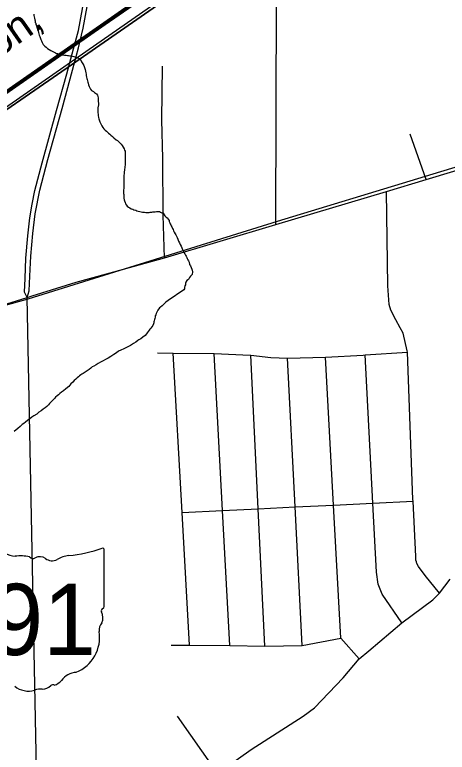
# Model space of a CAD drawing. Extents: x 0 to 44.3, y 0 to 22.
# Drawn here: x 3.367 to 4.168, y 16.349 to 17.715 of the extents above; entities that cross this region are included whole.
import ezdxf

# ---------------------------------------------------------------- set-up
doc = ezdxf.new("R2010")
doc.units = 0
for name, color, linetype in [('GM_X_City_Street', 7, 'Continuous'), ('GM_X_Corporation', 7, 'Continuous'), ('GM_X_County_Road', 7, 'Continuous'), ('GM_X_Minor_River', 7, 'Continuous'), ('GM_X_Rail_Line', 7, 'Continuous'), ('GM_X_Rail_Line_Text', 7, 'Continuous'), ('GM_X_State_Location', 7, 'Continuous'), ('GM_X_State_Route', 7, 'Continuous'), ('GM_X_State_Shield', 7, 'Continuous'), ('GM_X_US_Route', 7, 'Continuous')]:
    doc.layers.add(name, color=color, linetype=linetype)

msp = doc.modelspace()

# ---------------------------------------------------------------- linework, layer by layer
at = {"layer": 'GM_X_City_Street'}
for p, q in [((4.1283, 17.4097), (4.099, 17.4939)), ((3.7426, 16.3102), (3.6678, 16.4159))]:
    msp.add_line(p, q, dxfattribs=at)
for points in [[(3.644, 17.2645), (3.6416, 17.3439), (3.6409, 17.4487), (3.6393, 17.5202), (3.6402, 17.6194)], [(4.1533, 16.6438), (4.1268, 16.6764), (4.1141, 16.6933), (4.1114, 16.6988), (4.1106, 16.7017), (4.1097, 16.7046), (4.1092, 16.7115), (4.1044, 16.8141), (4.1042, 16.8173), (4.0938, 17.0899), (4.0937, 17.0925), (4.0861, 17.1252), (4.0805, 17.135), (4.0723, 17.15), (4.0631, 17.1681), (4.0603, 17.1786), (4.0573, 17.2131), (4.0551, 17.3878)], [(3.631, 17.0887), (3.6601, 17.088), (3.7358, 17.0875), (3.8024, 17.0845), (3.804, 17.0843), (3.8411, 17.0803), (3.8717, 17.0791), (3.9421, 17.081), (4.0122, 17.0847), (4.0155, 17.0849), (4.0938, 17.0899)], [(3.6902, 16.5474), (3.6769, 16.7931), (3.6601, 17.088)], [(3.7647, 16.5466), (3.7514, 16.7968), (3.7358, 17.0875)], [(3.8295, 16.5458), (3.8175, 16.8), (3.804, 17.0843)], [(3.8987, 16.5469), (3.8857, 16.8034), (3.8717, 17.0791)], [(4.0047, 16.5223), (3.9703, 16.5602), (3.957, 16.8069), (3.9421, 17.081)], [(4.0837, 16.5889), (4.0474, 16.6417), (4.0398, 16.6602), (4.0364, 16.6825), (4.0297, 16.8104), (4.0155, 17.0849)], [(3.6769, 16.7931), (3.7514, 16.7968), (3.8175, 16.8), (3.8857, 16.8034), (3.957, 16.8069), (4.0297, 16.8104), (4.1044, 16.8141)], [(3.6565, 16.5474), (3.6902, 16.5474), (3.7647, 16.5466), (3.8295, 16.5458), (3.8987, 16.5469), (3.9703, 16.5602)]]:
    msp.add_lwpolyline(points, dxfattribs=at)
at = {"layer": 'GM_X_Corporation'}
for points in [[(2.622, 17.8601), (2.6288, 17.5345), (2.6942, 17.1562), (2.7194, 17.1037), (2.8541, 17.1959), (3.4718, 17.6223), (3.8489, 17.8842)], [(3.8489, 17.8842), (3.4718, 17.6223), (2.8541, 17.1959), (2.7194, 17.1037), (2.7996, 16.9364), (2.8787, 16.9814), (2.9148, 16.9035), (2.9156, 16.875), (2.9192, 16.8391), (2.9204, 16.6966), (2.9251, 16.4817), (3.0704, 16.4866), (3.0702, 16.3994), (3.0821, 15.82), (3.1447, 15.8221), (3.1444, 15.7503), (3.6077, 15.7576), (3.6013, 15.9867), (3.6481, 15.9878), (3.6443, 16.103), (3.9637, 16.1137), (4.243, 16.3316)]]:
    msp.add_lwpolyline(points, dxfattribs=at)
at = {"layer": 'GM_X_County_Road'}
msp.add_line((3.8503, 17.3263), (3.8515, 17.8286), dxfattribs=at)
at = {"layer": 'GM_X_Minor_River'}
for points in [[(3.4018, 17.7157), (3.4022, 17.7134), (3.4026, 17.7107), (3.4034, 17.7088), (3.4038, 17.7054), (3.4042, 17.7035), (3.4046, 17.7008), (3.4054, 17.699), (3.4058, 17.6967), (3.4066, 17.6948), (3.4073, 17.6921), (3.4081, 17.6899), (3.4089, 17.6868), (3.4097, 17.6849), (3.4105, 17.6823), (3.4113, 17.6796), (3.4121, 17.6773), (3.4129, 17.6747), (3.4152, 17.669), (3.4164, 17.6663), (3.4175, 17.6633), (3.4195, 17.6599), (3.4222, 17.6569), (3.4245, 17.655), (3.4272, 17.6524), (3.4306, 17.6505), (3.4337, 17.6486), (3.4359, 17.6475), (3.4386, 17.646), (3.442, 17.6442), (3.444, 17.6434), (3.4459, 17.6431), (3.4478, 17.6423), (3.4504, 17.6416), (3.4523, 17.6408), (3.4558, 17.6405), (3.4588, 17.6401), (3.4618, 17.6398), (3.4641, 17.6394), (3.4664, 17.6391)], [(3.4664, 17.6391), (3.4687, 17.6387), (3.4706, 17.6387), (3.4736, 17.638), (3.4763, 17.6377), (3.479, 17.6365), (3.482, 17.6358), (3.4858, 17.6336), (3.4877, 17.6321), (3.4897, 17.6298), (3.4904, 17.6279), (3.4916, 17.6256), (3.4928, 17.6237), (3.4943, 17.6207), (3.4955, 17.6173), (3.4967, 17.6135), (3.4975, 17.6101), (3.4983, 17.6074), (3.4987, 17.6048), (3.4991, 17.6025), (3.4995, 17.5995), (3.5003, 17.5968), (3.5007, 17.5949), (3.5015, 17.5926), (3.5019, 17.59), (3.5023, 17.5881), (3.5034, 17.5851), (3.5042, 17.582), (3.5054, 17.5794), (3.5069, 17.5771), (3.5089, 17.5748), (3.5123, 17.5726), (3.5146, 17.5707), (3.5177, 17.5685), (3.52, 17.5662), (3.5212, 17.5609), (3.5212, 17.5575), (3.5217, 17.5483), (3.5206, 17.5426), (3.5207, 17.54), (3.5207, 17.5373), (3.5207, 17.5335), (3.5208, 17.5308), (3.5212, 17.5282), (3.522, 17.5244), (3.5224, 17.5221), (3.5235, 17.5187), (3.5243, 17.5168), (3.5255, 17.5141), (3.5267, 17.5119), (3.5278, 17.5092), (3.5298, 17.5062), (3.5313, 17.5036), (3.534, 17.5009), (3.5363, 17.499), (3.5382, 17.4972), (3.5401, 17.4953), (3.5424, 17.4938), (3.5443, 17.4919), (3.5478, 17.4893), (3.5501, 17.487), (3.5547, 17.4832), (3.5566, 17.4817), (3.5616, 17.4772), (3.5639, 17.4753), (3.5658, 17.4727), (3.5674, 17.4697), (3.5693, 17.4667), (3.5701, 17.4644), (3.5709, 17.4621), (3.5713, 17.4579), (3.5713, 17.4556), (3.5714, 17.453), (3.5714, 17.4507), (3.571, 17.4484), (3.5711, 17.445), (3.5711, 17.4431), (3.5711, 17.4404), (3.5708, 17.4374), (3.5704, 17.4324), (3.5697, 17.4275), (3.5694, 17.4233), (3.5691, 17.4203), (3.5687, 17.4176), (3.5688, 17.4145), (3.5684, 17.4119), (3.5684, 17.4088), (3.5685, 17.4062), (3.5685, 17.4035), (3.5685, 17.4008), (3.5686, 17.3982), (3.5686, 17.3955), (3.5686, 17.3929), (3.5683, 17.3906), (3.5683, 17.3887), (3.5683, 17.3864), (3.5683, 17.3841), (3.5684, 17.3818), (3.5684, 17.3795), (3.5684, 17.3773), (3.5688, 17.3754)], [(3.5688, 17.3754), (3.5692, 17.3723), (3.5696, 17.3701), (3.5708, 17.367), (3.572, 17.3648), (3.5735, 17.3621), (3.5747, 17.3602), (3.5774, 17.3583), (3.58, 17.3572), (3.5823, 17.3557), (3.5854, 17.3546), (3.5873, 17.3539), (3.5907, 17.3528), (3.5926, 17.352), (3.5953, 17.3513), (3.5983, 17.3506), (3.6006, 17.3498), (3.6029, 17.3495), (3.6048, 17.3491), (3.6071, 17.3491), (3.6093, 17.3488), (3.6112, 17.3488), (3.6139, 17.3488), (3.6158, 17.3488), (3.6177, 17.3492), (3.6207, 17.3493), (3.6226, 17.3497), (3.6245, 17.3501), (3.6268, 17.3501), (3.6294, 17.3505), (3.6313, 17.3505), (3.6344, 17.3505), (3.6367, 17.3494), (3.639, 17.3483), (3.6412, 17.3472), (3.6447, 17.3426), (3.647, 17.34), (3.6489, 17.3389), (3.6509, 17.3366), (3.6524, 17.3336), (3.6528, 17.3317), (3.6536, 17.3298), (3.6544, 17.3275), (3.6555, 17.3256), (3.6563, 17.3237), (3.6575, 17.3219), (3.6586, 17.3188), (3.6598, 17.3169), (3.6606, 17.315), (3.6621, 17.3124), (3.6637, 17.309), (3.6648, 17.3071), (3.6664, 17.3048), (3.6676, 17.3022), (3.6687, 17.2995), (3.6699, 17.2957), (3.6718, 17.2927), (3.673, 17.2893), (3.6746, 17.2863), (3.6761, 17.2832), (3.6773, 17.2802), (3.6788, 17.2776), (3.68, 17.2749), (3.6816, 17.2723), (3.6831, 17.2696), (3.6839, 17.2677), (3.6851, 17.2654), (3.6862, 17.2632), (3.6874, 17.2613), (3.6882, 17.2594), (3.6897, 17.2567), (3.6905, 17.2522), (3.6924, 17.2499), (3.6948, 17.2439), (3.6952, 17.2416), (3.696, 17.2386), (3.6949, 17.2336), (3.6923, 17.2309), (3.6904, 17.2286), (3.6882, 17.2244), (3.6852, 17.2229), (3.6837, 17.2198), (3.6829, 17.2175), (3.6826, 17.2148), (3.6819, 17.2126), (3.6811, 17.2099), (3.6808, 17.2072), (3.68, 17.2053)], [(3.68, 17.2053), (3.6506, 17.186), (3.6465, 17.1829), (3.6446, 17.1806), (3.642, 17.1783), (3.6394, 17.1759), (3.6368, 17.1736), (3.6349, 17.1724), (3.6319, 17.1678), (3.6297, 17.164), (3.6286, 17.1617), (3.6279, 17.1594), (3.6268, 17.1571), (3.6265, 17.1548), (3.6262, 17.1525), (3.6254, 17.1506), (3.6251, 17.1483), (3.6244, 17.146), (3.624, 17.1441), (3.6233, 17.1422), (3.6222, 17.1395), (3.6204, 17.1368), (3.6185, 17.1345), (3.617, 17.1326), (3.6156, 17.1307), (3.6137, 17.1284), (3.6119, 17.1261), (3.6108, 17.1241), (3.6082, 17.1211), (3.604, 17.1176), (3.5999, 17.1148), (3.5965, 17.1129), (3.5943, 17.1117), (3.5906, 17.1086), (3.5868, 17.1058), (3.5812, 17.1023), (3.5748, 17.0992), (3.5688, 17.096), (3.5628, 17.094), (3.559, 17.0917), (3.5549, 17.0889), (3.5504, 17.0854), (3.5448, 17.0819), (3.5395, 17.0792), (3.5252, 17.0713), (3.5211, 17.0689), (3.5174, 17.0666), (3.5128, 17.0642), (3.5102, 17.0627), (3.5076, 17.0607), (3.5042, 17.058), (3.5005, 17.0553), (3.4967, 17.0529), (3.4934, 17.0506), (3.4911, 17.0494), (3.4892, 17.0479), (3.4866, 17.0459), (3.4844, 17.0443), (3.4821, 17.0424), (3.4795, 17.0401), (3.4769, 17.0374), (3.4739, 17.0347), (3.4706, 17.0312), (3.4665, 17.0265), (3.4613, 17.0223), (3.4568, 17.0184), (3.453, 17.0157), (3.45, 17.0133), (3.4474, 17.011), (3.4452, 17.0091), (3.4422, 17.0064), (3.44, 17.0044), (3.4381, 17.0025), (3.4362, 17.0005), (3.4344, 16.9986), (3.4329, 16.9967), (3.431, 16.9951), (3.4288, 16.9924), (3.4262, 16.9897), (3.4228, 16.987), (3.4191, 16.9843), (3.4157, 16.9812), (3.4112, 16.9788), (3.4075, 16.9753), (3.4022, 16.9722), (3.3981, 16.9695), (3.3944, 16.9664), (3.3903, 16.9632), (3.3865, 16.9605), (3.3832, 16.9582), (3.3802, 16.9558), (3.3768, 16.9524), (3.3723, 16.9485), (3.3656, 16.943)]]:
    msp.add_lwpolyline(points, dxfattribs=at)
at = {"layer": 'GM_X_Rail_Line'}
for points in [[(5.0399, 18.1234), (4.8858, 17.826), (4.8521, 17.786), (4.6557, 17.5832), (4.6326, 17.5692), (3.8528, 17.3319), (3.3907, 17.1879), (3.1392, 17.1176), (3.0576, 17.079), (2.5475, 16.7844), (2.4777, 16.7406), (2.4046, 16.6684), (2.3118, 16.5782), (2.1, 16.3666)], [(2.1, 16.6739), (2.1539, 16.7114), (2.7235, 17.1075), (3.4981, 17.6468), (4.1115, 18.074)], [(2.1, 16.7049), (2.1048, 16.7082), (2.3747, 16.896), (2.5221, 16.9973), (2.7533, 17.1586), (2.9361, 17.286), (3.5315, 17.7008), (3.6785, 17.8033)], [(2.1, 16.702), (2.1061, 16.7063), (2.3761, 16.894), (2.5234, 16.9954), (2.7546, 17.1567), (2.9374, 17.2841), (3.5329, 17.6989), (3.6799, 17.8014)], [(2.1, 16.6992), (2.1074, 16.7044), (2.3774, 16.8921), (2.5248, 16.9934), (2.756, 17.1548), (2.9388, 17.2822), (3.5342, 17.697), (3.6813, 17.7995)]]:
    msp.add_lwpolyline(points, dxfattribs=at)
at = {"layer": 'GM_X_State_Route'}
for points in [[(3.3895, 17.1913), (3.3848, 17.2012), (3.3858, 17.2265), (3.3874, 17.2638), (3.3911, 17.3057), (3.3945, 17.3385), (3.3989, 17.3639), (3.4037, 17.3894), (3.4173, 17.4409), (3.4437, 17.5374), (3.463, 17.6056), (3.4757, 17.6515), (3.4845, 17.6856), (3.4918, 17.7257), (3.4981, 17.7749), (3.5012, 17.8244), (3.5027, 17.8567), (3.5025, 17.8692)], [(3.4762, 17.6213), (3.4849, 17.6537), (3.4932, 17.6899), (3.5005, 17.73), (3.5068, 17.7791), (3.5099, 17.8287), (3.5114, 17.8609), (3.5112, 17.8745)], [(3.3895, 17.1913), (3.3934, 17.2036), (3.3945, 17.2308), (3.3961, 17.2681), (3.3998, 17.31), (3.4046, 17.3464), (3.413, 17.39), (3.4281, 17.4466), (3.4542, 17.5414), (3.4737, 17.6122), (3.4762, 17.6213)], [(3.4115, 15.7987), (3.4155, 15.8789), (3.4136, 15.9738), (3.3895, 17.1913)], [(3.4136, 15.9738), (3.4676, 16.0352), (3.5607, 16.1372), (3.6199, 16.1964), (3.6514, 16.2266), (3.689, 16.2649), (3.7426, 16.3102), (3.8043, 16.354), (3.9005, 16.4157), (3.9217, 16.4314), (3.9751, 16.4872), (4.0047, 16.5223), (4.0223, 16.5368), (4.0837, 16.5889), (4.141, 16.6312), (4.1533, 16.6438), (4.1731, 16.6697)]]:
    msp.add_lwpolyline(points, dxfattribs=at)
at = {"layer": 'GM_X_State_Shield'}
for q in [(3.5321, 16.7236), (3.5321, 16.6189)]:
    msp.add_line((3.5321, 16.6189), q, dxfattribs=at)
for centre, radius, start, end in [((3.3667, 16.7419), 0.0296, 231.6195, 271.1119), ((3.4382, 16.9915), 0.2796, 275.8445, 288.9065), ((3.5292, 16.724), 0.00294, 351.8621, 97.738), ((3.3765, 16.6063), 0.1064, 80.4867, 94.9883), ((3.4006, 16.7166), 0.00855, 219.7921, 297.1024), ((3.4132, 16.6935), 0.0178, 54.4667, 119.1411), ((3.4361, 16.7252), 0.0214, 233.8562, 294.8282), ((3.4739, 16.6575), 0.0563, 97.3462, 120.7689), ((3.5314, 16.6112), 0.00454, 107.944, 210.337), ((3.5025, 16.598), 0.0273, 340.033, 23.6496), ((3.529, 16.6185), 0.00314, 289.6038, 7.7341), ((3.5426, 16.5751), 0.0198, 136.8065, 186.9296), ((3.4539, 16.5618), 0.0699, 292.3089, 8.9858), ((3.4833, 16.4589), 0.0383, 94.4031, 142.5768), ((3.392, 16.5025), 0.0401, 230.7004, 286.2918), ((3.4181, 16.4875), 0.0214, 268.777, 315.5493), ((3.4374, 16.4682), 0.00601, 65.7517, 132.6484), ((3.4348, 16.4957), 0.0226, 282.8732, 323.2771), ((3.4151, 16.4333), 0.0329, 85.6951, 111.2099)]:
    msp.add_arc(centre, radius, start, end, dxfattribs=at)
at = {"layer": 'GM_X_US_Route'}
for points in [[(3.5683, 17.2439), (3.644, 17.2645), (3.8503, 17.3263), (4.0551, 17.3878), (4.1283, 17.4097), (4.3396, 17.4731), (4.4345, 17.5015), (4.5978, 17.5505)], [(3.3989, 17.1943), (3.4803, 17.2198), (3.5683, 17.2439)], [(3.3421, 17.1765), (3.3895, 17.1913), (3.3989, 17.1943)]]:
    msp.add_lwpolyline(points, dxfattribs=at)

# ---------------------------------------------------------------- texts
at = {"layer": 'GM_X_Rail_Line_Text'}
msp.add_text('Transportation,', height=0.056629, rotation=34.8547, dxfattribs=at).set_placement((3.0046, 17.403))
at = {"layer": 'GM_X_State_Location'}
for s in ['s', 'r']:
    msp.add_text(s, height=0.000189, dxfattribs=at).set_placement((3.3973, 16.6018))
at = {"layer": 'GM_X_State_Shield'}
msp.add_text('91', height=0.13184, dxfattribs=at).set_placement((3.3212, 16.5292))

doc.saveas('drawing.dxf')
